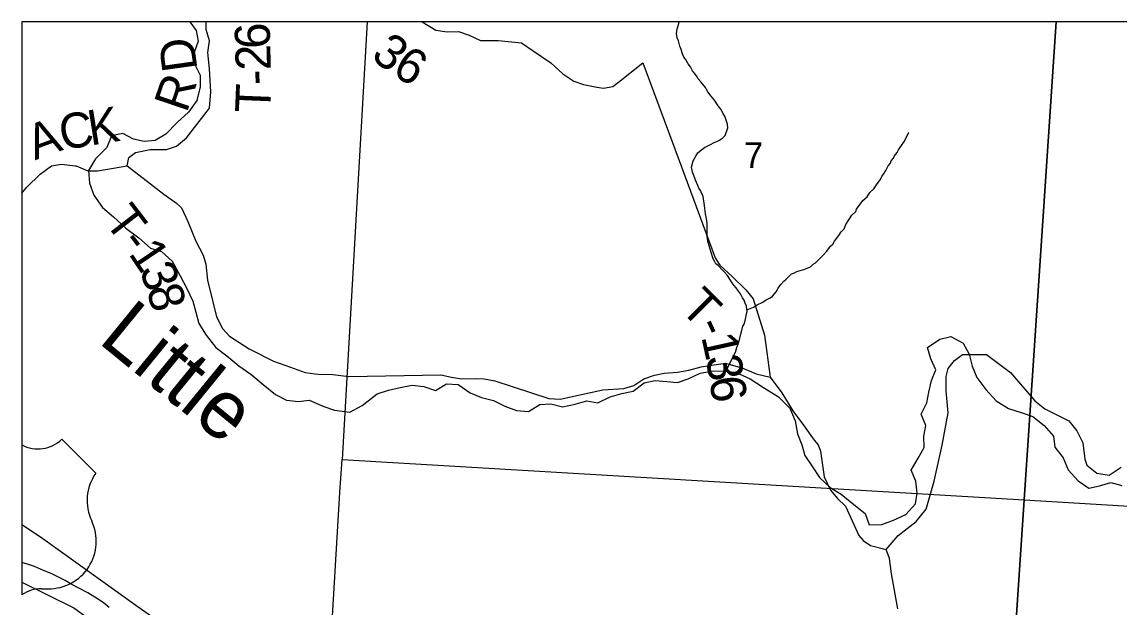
# Model space of a CAD drawing. Extents: x 1949938.81 to 1949945.61, y 152207.65 to 152214.09.
# Drawn here: x 1949938.807 to 1949940.583, y 152213.141 to 152214.087 of the extents above; entities that cross this region are included whole.
import ezdxf

# ---------------------------------------------------------------- set-up
doc = ezdxf.new("R2010")
doc.units = 0
for name, color, linetype in [('GM_X_County', 7, 'Continuous'), ('GM_X_County_Road', 7, 'Continuous'), ('GM_X_Major_River', 7, 'Continuous'), ('GM_X_Minor_River', 7, 'Continuous'), ('GM_X_Minor_River_Text', 7, 'Continuous'), ('GM_X_Section', 7, 'Continuous'), ('GM_X_Section_Text', 7, 'Continuous'), ('GM_X_Township', 7, 'Continuous'), ('GM_X_Township_Road', 7, 'Continuous'), ('GM_X_Township_Road_Text', 7, 'Continuous'), ('GM_X_Township_ROW', 7, 'Continuous'), ('GM_X_US_Route', 7, 'Continuous'), ('GM_X_US_Shield', 7, 'Continuous')]:
    doc.layers.add(name, color=color, linetype=linetype)

msp = doc.modelspace()

# ---------------------------------------------------------------- linework, layer by layer
at = {"layer": 'GM_X_County'}
for points in [[(1949945.6069, 152208.8266), (1949945.6069, 152214.0874), (1949938.8069, 152214.0874), (1949938.8069, 152213.1813)], [(1949938.8069, 152213.1813), (1949938.8908, 152213.14), (1949939.0267, 152213.041), (1949939.1111, 152212.9977), (1949939.166, 152212.9381), (1949939.244, 152212.8721), (1949939.3272, 152212.7909), (1949939.4464, 152212.5807), (1949939.6012, 152212.2498), (1949939.6822, 152212.0255), (1949939.7473, 152211.904), (1949939.7481, 152211.8801), (1949939.7311, 152211.8376), (1949939.7258, 152211.7457)]]:
    msp.add_lwpolyline(points, dxfattribs=at)
at = {"layer": 'GM_X_County_Road'}
msp.add_lwpolyline([(1949940.225, 152213.1383), (1949940.2143, 152213.1949), (1949940.2111, 152213.2198), (1949940.2057, 152213.234), (1949940.2252, 152213.2568), (1949940.2545, 152213.2796), (1949940.2707, 152213.2991), (1949940.2837, 152213.3446), (1949940.2968, 152213.4031), (1949940.3065, 152213.4551), (1949940.3033, 152213.4909), (1949940.3033, 152213.5137), (1949940.3065, 152213.5267), (1949940.3163, 152213.5397), (1949940.3293, 152213.5495), (1949940.3683, 152213.5495), (1949940.4074, 152213.5202), (1949940.4464, 152213.4747), (1949940.4627, 152213.4616), (1949940.5017, 152213.4421), (1949940.5147, 152213.4259), (1949940.5245, 152213.4064), (1949940.5277, 152213.3803), (1949940.531, 152213.3706), (1949940.5472, 152213.3576), (1949940.5668, 152213.3543), (1949940.5863, 152213.3673)], dxfattribs=at)
at = {"layer": 'GM_X_Major_River'}
msp.add_lwpolyline([(1949938.9482, 152213.1403), (1949938.9384, 152213.1482), (1949938.9248, 152213.157), (1949938.9135, 152213.1638), (1949938.8991, 152213.1714), (1949938.8866, 152213.1782), (1949938.8768, 152213.1839), (1949938.8541, 152213.1953), (1949938.8416, 152213.2002), (1949938.8272, 152213.2067), (1949938.8174, 152213.2097), (1949938.8069, 152213.2129)], dxfattribs=at)
at = {"layer": 'GM_X_Minor_River'}
for points in [[(1949939.0786, 152214.0874), (1949939.089, 152214.0736), (1949939.0919, 152214.0561), (1949939.0858, 152214.0379), (1949939.0857, 152214.0205), (1949939.0955, 152214.0015), (1949939.0954, 152213.9825), (1949939.09, 152213.9605), (1949939.0763, 152213.9416), (1949939.058, 152213.9249), (1949939.0398, 152213.906), (1949939.0223, 152213.8954), (1949939.0049, 152213.894), (1949938.9875, 152213.8979), (1949938.9701, 152213.907), (1949938.9519, 152213.9033), (1949938.9443, 152213.8843), (1949938.926, 152213.8662), (1949938.9146, 152213.8473), (1949938.916, 152213.8268), (1949938.9235, 152213.807), (1949938.9371, 152213.7872), (1949938.9552, 152213.772), (1949938.9748, 152213.7537), (1949938.9959, 152213.7384), (1949939.0148, 152213.7216), (1949939.0329, 152213.7163), (1949939.0503, 152213.7003), (1949939.0631, 152213.6767), (1949939.0736, 152213.6561), (1949939.0833, 152213.6356), (1949939.0886, 152213.6181), (1949939.093, 152213.5999), (1949939.1051, 152213.5809), (1949939.1209, 152213.5611), (1949939.1383, 152213.5474), (1949939.1579, 152213.5313), (1949939.1775, 152213.5176), (1949939.1971, 152213.5008), (1949939.2175, 152213.4848), (1949939.2349, 152213.4756), (1949939.2546, 152213.4733), (1949939.272, 152213.4755), (1949939.2954, 152213.4656), (1949939.3128, 152213.4594), (1949939.3378, 152213.4563), (1949939.3576, 152213.4668), (1949939.3819, 152213.4857), (1949939.4001, 152213.4917), (1949939.419, 152213.4962), (1949939.4387, 152213.4999), (1949939.4577, 152213.4976), (1949939.4766, 152213.4915), (1949939.494, 152213.502), (1949939.513, 152213.5012), (1949939.5326, 152213.4875), (1949939.5507, 152213.4798), (1949939.5704, 152213.4752)], [(1949939.9462, 152213.5224), (1949939.9622, 152213.5535), (1949939.9642, 152213.561), (1949939.967, 152213.5682), (1949939.969, 152213.5754), (1949939.9703, 152213.5807), (1949939.9719, 152213.586), (1949939.9739, 152213.5951), (1949939.9759, 152213.5988), (1949939.9775, 152213.6045), (1949939.9787, 152213.6094), (1949939.9796, 152213.6151), (1949939.9808, 152213.6189), (1949939.9805, 152213.623), (1949939.9798, 152213.6276), (1949939.9776, 152213.6326), (1949939.9758, 152213.6376), (1949939.9736, 152213.641), (1949939.9703, 152213.6475), (1949939.967, 152213.6518), (1949939.9633, 152213.6575), (1949939.9592, 152213.6618), (1949939.9555, 152213.6671), (1949939.9529, 152213.6714), (1949939.9492, 152213.6771), (1949939.9444, 152213.6829), (1949939.9407, 152213.686), (1949939.934, 152213.6933), (1949939.9303, 152213.6964), (1949939.9281, 152213.7003), (1949939.9258, 152213.7041), (1949939.9219, 152213.7163), (1949939.9212, 152213.7201), (1949939.9176, 152213.7308), (1949939.9163, 152213.7399), (1949939.9164, 152213.7483), (1949939.9161, 152213.7521), (1949939.9161, 152213.7555), (1949939.9159, 152213.7616), (1949939.9152, 152213.7688), (1949939.9135, 152213.7772), (1949939.9125, 152213.7856), (1949939.9112, 152213.7951), (1949939.9101, 152213.8008), (1949939.9095, 152213.8054), (1949939.9076, 152213.8092), (1949939.9051, 152213.8149), (1949939.9025, 152213.8188), (1949939.901, 152213.823), (1949939.897, 152213.8314), (1949939.896, 152213.8348), (1949939.8923, 152213.8444), (1949939.891, 152213.8524), (1949939.8934, 152213.8626), (1949939.8981, 152213.8716), (1949939.9012, 152213.8758), (1949939.9074, 152213.8813), (1949939.9116, 152213.8843), (1949939.917, 152213.8873), (1949939.9204, 152213.8887), (1949939.9284, 152213.8928), (1949939.9318, 152213.8938), (1949939.9361, 152213.8964), (1949939.9414, 152213.8998), (1949939.9453, 152213.9035), (1949939.9497, 152213.9159), (1949939.949, 152213.922), (1949939.9476, 152213.927), (1949939.9447, 152213.935), (1949939.9421, 152213.9388), (1949939.9403, 152213.9423), (1949939.9384, 152213.9461), (1949939.934, 152213.9519), (1949939.9281, 152213.9611), (1949939.9225, 152213.9673), (1949939.9174, 152213.9742), (1949939.9151, 152213.978), (1949939.9137, 152213.9815), (1949939.9059, 152213.9907), (1949939.9018, 152213.9954), (1949939.8989, 152214), (1949939.8952, 152214.005), (1949939.8926, 152214.0084), (1949939.8889, 152214.0146), (1949939.8852, 152214.0199), (1949939.8834, 152214.0234), (1949939.8812, 152214.0272), (1949939.8786, 152214.0307), (1949939.876, 152214.0357), (1949939.8739, 152214.0429), (1949939.8717, 152214.0483), (1949939.8696, 152214.057), (1949939.8674, 152214.0616), (1949939.8667, 152214.0688), (1949939.8668, 152214.0723), (1949939.8676, 152214.0764), (1949939.8701, 152214.0851), (1949939.8709, 152214.0874)], [(1949939.9801, 152213.6215), (1949939.9858, 152213.6241), (1949939.9911, 152213.6259), (1949939.9969, 152213.63), (1949940.0061, 152213.6344), (1949940.0118, 152213.6377), (1949940.0183, 152213.6414), (1949940.0221, 152213.644), (1949940.0279, 152213.6511), (1949940.0311, 152213.6567), (1949940.0353, 152213.6627), (1949940.04, 152213.668), (1949940.0442, 152213.6713), (1949940.0527, 152213.6799), (1949940.0573, 152213.6817), (1949940.0615, 152213.6839), (1949940.0649, 152213.685), (1949940.0725, 152213.6872), (1949940.0782, 152213.689), (1949940.0832, 152213.6912), (1949940.0878, 152213.6956), (1949940.0913, 152213.6979), (1949940.0986, 152213.7046), (1949940.104, 152213.7102), (1949940.1098, 152213.7165), (1949940.1156, 152213.7248), (1949940.1194, 152213.7278), (1949940.1222, 152213.7326), (1949940.1295, 152213.742), (1949940.133, 152213.748), (1949940.1377, 152213.7529), (1949940.1408, 152213.76), (1949940.1506, 152213.7747), (1949940.1567, 152213.781), (1949940.1579, 152213.7848), (1949940.1653, 152213.7949), (1949940.168, 152213.7987), (1949940.1749, 152213.8043), (1949940.1796, 152213.8114), (1949940.1862, 152213.8177), (1949940.1916, 152213.8253), (1949940.1967, 152213.8324), (1949940.199, 152213.8373), (1949940.2029, 152213.8429), (1949940.2052, 152213.8474), (1949940.2092, 152213.8546), (1949940.2127, 152213.8591), (1949940.2142, 152213.8628), (1949940.2177, 152213.867), (1949940.2193, 152213.8711), (1949940.2236, 152213.876), (1949940.2259, 152213.8805), (1949940.2329, 152213.8906), (1949940.2356, 152213.8947), (1949940.2372, 152213.8985), (1949940.2392, 152213.9019), (1949940.2423, 152213.9083), (1949940.2428, 152213.9089)], [(1949939.5704, 152213.4752), (1949939.5885, 152213.466), (1949939.6074, 152213.4591), (1949939.6271, 152213.4575), (1949939.6454, 152213.4688), (1949939.6628, 152213.4695), (1949939.6817, 152213.4649), (1949939.7022, 152213.4694), (1949939.7211, 152213.4746), (1949939.7393, 152213.4715), (1949939.759, 152213.4813), (1949939.778, 152213.4866), (1949939.7962, 152213.4903), (1949939.8144, 152213.5039), (1949939.8318, 152213.5076), (1949939.8508, 152213.506), (1949939.8682, 152213.5044), (1949939.8856, 152213.5104), (1949939.9046, 152213.5195), (1949939.9266, 152213.5232), (1949939.9462, 152213.5224), (1949939.9682, 152213.5185), (1949939.9856, 152213.5101), (1949940.0075, 152213.4963), (1949940.0317, 152213.4811), (1949940.0498, 152213.4628), (1949940.0588, 152213.4423), (1949940.0625, 152213.421), (1949940.0692, 152213.4035), (1949940.0744, 152213.386), (1949940.0865, 152213.3678), (1949940.0978, 152213.3503), (1949940.1151, 152213.3343), (1949940.1332, 152213.3236), (1949940.1536, 152213.3068), (1949940.1717, 152213.2923), (1949940.1785, 152213.2741), (1949940.1989, 152213.2747), (1949940.2179, 152213.2815), (1949940.2376, 152213.2905), (1949940.2536, 152213.3079), (1949940.2559, 152213.3254), (1949940.2537, 152213.3444), (1949940.2462, 152213.3626), (1949940.2577, 152213.3816), (1949940.2676, 152213.399), (1949940.2669, 152213.4172), (1949940.27, 152213.4346), (1949940.2625, 152213.4529), (1949940.2717, 152213.4711), (1949940.2748, 152213.4885), (1949940.2794, 152213.5075), (1949940.2863, 152213.5249), (1949940.2781, 152213.5424), (1949940.2728, 152213.5606), (1949940.2926, 152213.5742), (1949940.3108, 152213.5787), (1949940.3304, 152213.568), (1949940.3402, 152213.5498), (1949940.3454, 152213.5308), (1949940.3529, 152213.5125), (1949940.3672, 152213.4927), (1949940.3838, 152213.4745), (1949940.4042, 152213.4622), (1949940.4261, 152213.4553), (1949940.4435, 152213.4492), (1949940.4616, 152213.4347), (1949940.4767, 152213.4172), (1949940.4789, 152213.3997), (1949940.4925, 152213.3822), (1949940.5007, 152213.3632), (1949940.5165, 152213.3449), (1949940.5339, 152213.3335), (1949940.5514, 152213.3372), (1949940.5696, 152213.3424), (1949940.5877, 152213.3378)]]:
    msp.add_lwpolyline(points, dxfattribs=at)
at = {"layer": 'GM_X_Section'}
for p, q in [((1949940.4809, 152214.0874), (1949939.3659, 152214.0874)), ((1949941.5608, 152214.0874), (1949940.4809, 152214.0874))]:
    msp.add_line(p, q, dxfattribs=at)
for points in [[(1949939.3659, 152214.0874), (1949939.325, 152213.3794), (1949940.4294, 152213.3146), (1949940.4809, 152214.0874)], [(1949940.4809, 152214.0874), (1949940.4294, 152213.3146), (1949941.5133, 152213.2491), (1949941.5608, 152214.0874)], [(1949939.2929, 152212.8444), (1949939.3216, 152213.3263), (1949939.325, 152213.3794), (1949940.4294, 152213.3146), (1949940.3609, 152212.2864)]]:
    msp.add_lwpolyline(points, dxfattribs=at)
msp.add_lwpolyline([(1949941.5133, 152213.2491), (1949941.4524, 152212.2232), (1949940.3609, 152212.2864), (1949940.4294, 152213.3146)], close=True, dxfattribs=at)
at = {"layer": 'GM_X_Township'}
for points in [[(1949942.6839, 152214.0874), (1949938.8069, 152214.0874), (1949938.8069, 152213.1813)], [(1949938.8069, 152213.1813), (1949938.8908, 152213.14), (1949939.0267, 152213.041), (1949939.1111, 152212.9977), (1949939.166, 152212.9381), (1949939.244, 152212.8721), (1949939.3272, 152212.7909), (1949939.4464, 152212.5807), (1949939.6012, 152212.2498), (1949939.6822, 152212.0255), (1949939.7473, 152211.904), (1949939.7481, 152211.8801), (1949939.7311, 152211.8376), (1949939.7258, 152211.7457)]]:
    msp.add_lwpolyline(points, dxfattribs=at)
at = {"layer": 'GM_X_Township_Road'}
for points in [[(1949938.9772, 152213.8547), (1949938.9799, 152213.868), (1949938.9905, 152213.876), (1949939.0145, 152213.8813), (1949939.0411, 152213.8813), (1949939.057, 152213.8866), (1949939.073, 152213.8999), (1949939.1103, 152213.9478), (1949939.1129, 152213.9744), (1949939.1103, 152214.0116), (1949939.1076, 152214.0382), (1949939.1103, 152214.0568), (1949939.1049, 152214.0754), (1949939.1049, 152214.0874)], [(1949939.4548, 152214.0874), (1949939.4768, 152214.074), (1949939.4954, 152214.0713), (1949939.5136, 152214.0721), (1949939.531, 152214.066), (1949939.5492, 152214.0573), (1949939.5776, 152214.0573), (1949939.5995, 152214.0554), (1949939.6158, 152214.0535), (1949939.6344, 152214.0409), (1949939.6632, 152214.0212), (1949939.6825, 152214.0037), (1949939.7003, 152213.9919), (1949939.7158, 152213.9862), (1949939.7374, 152213.9817), (1949939.7484, 152213.9801), (1949939.7635, 152213.9832), (1949939.7726, 152213.99), (1949939.812, 152214.0211), (1949939.8637, 152213.882)], [(1949938.8069, 152213.8107), (1949938.8149, 152213.8202), (1949938.8362, 152213.8414), (1949938.8549, 152213.8547), (1949938.8708, 152213.8574), (1949938.8928, 152213.8549), (1949938.8948, 152213.8547), (1949938.9134, 152213.8467), (1949938.9294, 152213.8467), (1949938.9453, 152213.8494), (1949938.9772, 152213.8547)], [(1949938.9772, 152213.8547), (1949939.0081, 152213.8307), (1949939.0366, 152213.8086), (1949939.0571, 152213.7945), (1949939.0654, 152213.7869), (1949939.0752, 152213.7649), (1949939.0881, 152213.733), (1949939.1002, 152213.7102), (1949939.1044, 152213.6958), (1949939.107, 152213.67), (1949939.1161, 152213.6347), (1949939.1218, 152213.6104), (1949939.1316, 152213.5918), (1949939.143, 152213.5789), (1949939.1748, 152213.5588), (1949939.2142, 152213.5387), (1949939.2415, 152213.5291), (1949939.2653, 152213.5204), (1949939.2814, 152213.5184)], [(1949939.9354, 152213.6958), (1949939.9366, 152213.6939), (1949939.9566, 152213.6757), (1949939.979, 152213.654), (1949939.9907, 152213.6396), (1949940.0089, 152213.5808), (1949940.0184, 152213.5128)], [(1949939.2814, 152213.5184), (1949939.2869, 152213.5177), (1949939.3104, 152213.5173), (1949939.3362, 152213.5139), (1949939.485, 152213.5165), (1949939.5021, 152213.5127), (1949939.5184, 152213.5104), (1949939.5403, 152213.5108), (1949939.5551, 152213.5104), (1949939.5722, 152213.507), (1949939.6596, 152213.4785), (1949939.6782, 152213.4773), (1949939.7475, 152213.4921), (1949939.7812, 152213.4947), (1949939.7975, 152213.4996), (1949939.8138, 152213.5099), (1949939.8309, 152213.5163), (1949939.8464, 152213.5194), (1949939.868, 152213.5209), (1949939.8865, 152213.5243), (1949939.9066, 152213.5296), (1949939.9271, 152213.533), (1949939.946, 152213.5353), (1949939.974, 152213.5276), (1949939.9956, 152213.5185), (1949940.0184, 152213.5128), (1949940.0369, 152213.4874), (1949940.0547, 152213.4582), (1949940.0721, 152213.4354), (1949940.0892, 152213.4107), (1949940.0956, 152213.4035), (1949940.0998, 152213.3932), (1949940.1058, 152213.3515), (1949940.116, 152213.3302), (1949940.1274, 152213.3166), (1949940.1399, 152213.304), (1949940.1619, 152213.257), (1949940.1687, 152213.2486), (1949940.1804, 152213.2403), (1949940.2057, 152213.234)]]:
    msp.add_lwpolyline(points, dxfattribs=at)
at = {"layer": 'GM_X_Township_ROW'}
msp.add_lwpolyline([(1949939.8637, 152213.882), (1949939.929, 152213.706), (1949939.9354, 152213.6958)], dxfattribs=at)
at = {"layer": 'GM_X_US_Route'}
msp.add_lwpolyline([(1949938.8069, 152213.2746), (1949938.8368, 152213.2545), (1949938.9951, 152213.1414), (1949939.189, 152213.0058), (1949939.4205, 152212.855), (1949939.5354, 152212.7798), (1949939.5633, 152212.7584)], dxfattribs=at)
at = {"layer": 'GM_X_US_Shield'}
for p, q in [((1949938.8069, 152213.4032), (1949938.8069, 152213.1607)), ((1949938.9263, 152213.3574), (1949938.8714, 152213.4123)), ((1949938.8384, 152213.1706), (1949938.8494, 152213.1706))]:
    msp.add_line(p, q, dxfattribs=at)
for centre, radius, start, end in [((1949938.8329, 152213.4516), 0.0549, 241.68, 314.427), ((1949938.9893, 152213.3133), 0.0769, 144.9991, 205.4529), ((1949938.8503, 152213.2475), 0.0769, 269.3617, 25.1681), ((1949938.8384, 152213.1157), 0.0549, 90, 125.0573)]:
    msp.add_arc(centre, radius, start, end, dxfattribs=at)

# ---------------------------------------------------------------- texts
at = {"layer": 'GM_X_Minor_River_Text'}
msp.add_text('Little', height=0.09468, rotation=320.7841, dxfattribs=at).set_placement((1949938.9283, 152213.5701))
at = {"layer": 'GM_X_Section_Text'}
msp.add_text('7', height=0.0419, rotation=0, dxfattribs=at).set_placement((1949939.9757, 152213.851))
at = {"layer": 'GM_X_Township_Road_Text'}
for s, rotation, p in [('6', 91.8867, (1949939.209, 152214.0449)), ('D', 97.9096, (1949939.0912, 152214.0109)), ('3', 321.2677, (1949939.3699, 152214.03)), ('2', 91.5319, (1949939.2099, 152214.0095)), ('6', 328.8432, (1949939.404, 152214.0034)), ('-', 90.9404, (1949939.2103, 152213.9855)), ('R', 71.2574, (1949939.0735, 152213.9388)), ('T', 87.6723, (1949939.2085, 152213.9395)), ('K', 9.0895, (1949938.9179, 152213.8874)), ('C', 9.3273, (1949938.8719, 152213.8798)), ('A', 19.9975, (1949938.8276, 152213.8634)), ('T', 307.6203, (1949938.9389, 152213.7643)), ('-', 306.948, (1949938.9648, 152213.7308)), ('1', 304.0213, (1949938.9783, 152213.7128)), ('3', 290.6231, (1949938.9963, 152213.6869)), ('8', 285.4606, (1949939.0082, 152213.6554)), ('T', 315.014, (1949939.8706, 152213.6224)), ('-', 294.8708, (1949939.8976, 152213.5967)), ('1', 282.4413, (1949939.9064, 152213.5786)), ('3', 279.1194, (1949939.9138, 152213.5452)), ('6', 278.5768, (1949939.9193, 152213.5108))]:
    msp.add_text(s, height=0.0568, rotation=rotation, dxfattribs=at).set_placement(p)

doc.saveas('drawing.dxf')
